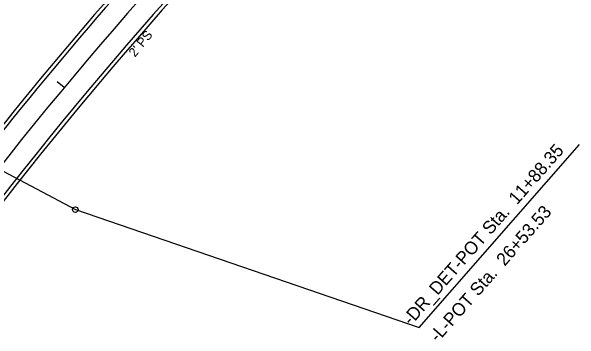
# Model space of a CAD drawing. Extents: x 2189637 to 2190858, y 386969 to 388736.
# Drawn here: x 2190461.8 to 2190771, y 388043.6 to 388222 of the extents above; entities that cross this region are included whole.
import ezdxf

# ---------------------------------------------------------------- set-up
doc = ezdxf.new("R2010")
doc.units = 0
for name, color, linetype in [('Exist Environmental Wetland Boundary Cogo Point CELL', 7, 'Continuous'), ('Exist Horizontal Alignment Tick Label', 7, 'Continuous'), ('Exist Hydro Swamp or Marsh', 7, 'Continuous'), ('Exist Property Corner CELL', 7, 'Continuous'), ('Exist Property Corner Cogo Elevation', 7, 'Continuous'), ('Exist Roads EOT', 7, 'Continuous')]:
    doc.layers.add(name, color=color, linetype=linetype)

msp = doc.modelspace()

# ---------------------------------------------------------------- linework, layer by layer
at = {"layer": 'Exist Environmental Wetland Boundary Cogo Point CELL'}
msp.add_line((2190330.06, 388202.3), (2190496.57, 388114.25), dxfattribs=at)
msp.add_arc((2192257.95, 386708.79), 2300, 135.25499, 144.20184, dxfattribs=at)
at = {"layer": 'Exist Horizontal Alignment Tick Label'}
msp.add_line((2190490.48, 388180.54), (2190486.64, 388183.74), dxfattribs=at)
at = {"layer": 'Exist Hydro Swamp or Marsh'}
for radius, start, end in [(2311, 135.25499, 141.00543), (2289, 135.35973, 144.20184), (2311, 141.00543, 144.20184)]:
    msp.add_arc((2192257.95, 386708.79), radius, start, end, dxfattribs=at)
at = {"layer": 'Exist Property Corner CELL'}
for radius, start, end in [(2313, 135.25499, 141.26353), (2287, 135.97689, 144.20184)]:
    msp.add_arc((2192257.95, 386708.79), radius, start, end, dxfattribs=at)
at = {"layer": 'Exist Property Corner Cogo Elevation'}
for p, q in [((2190683.68, 388050.25), (2190771.04, 388149.62)), ((2190496.57, 388114.25), (2190683.68, 388050.25))]:
    msp.add_line(p, q, dxfattribs=at)
msp.add_circle((2190496.57, 388114.25), 1.5, dxfattribs=at)

# ---------------------------------------------------------------- texts
for s, p in [('-DR_DET-POT Sta.  11+88.35', (2190679.26, 388050.9)), ('-L-POT Sta.  26+53.53', (2190693.85, 388041.74))]:
    msp.add_text(s, height=7, rotation=48.6794, dxfattribs=at).set_placement(p)
at = {"layer": 'Exist Roads EOT'}
msp.add_text("2' PS", height=5, rotation=50.9608, dxfattribs=at).set_placement((2190529.02, 388196.81))

doc.saveas('drawing.dxf')
